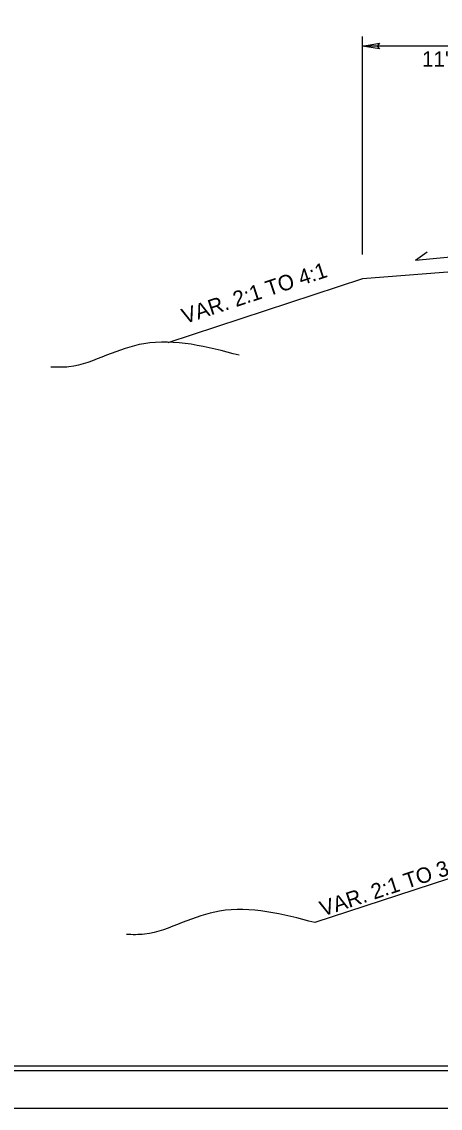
# Model space of a CAD drawing. Extents: x 2532463 to 2534146, y 189689 to 190784.
# Drawn here: x 2533037 to 2533260, y 189689 to 190267 of the extents above; entities that cross this region are included whole.
import ezdxf

# ---------------------------------------------------------------- set-up
doc = ezdxf.new("R2010")
doc.units = 0
for name, color, linetype in [('Old_Level_1', 7, 'Continuous'), ('Old_Level_10', 7, 'Continuous'), ('Old_Level_18', 7, 'Continuous'), ('Old_Level_2', 7, 'Continuous'), ('Old_Level_3', 7, 'Continuous'), ('Old_Level_42', 7, 'Continuous'), ('Old_Level_50', 7, 'Continuous'), ('Old_Level_51', 7, 'Continuous')]:
    doc.layers.add(name, color=color, linetype=linetype)

msp = doc.modelspace()

# ---------------------------------------------------------------- linework, layer by layer
at = {"layer": 'Old_Level_1'}
for p, q in [((2533296.94, 190136.17), (2533218.42, 190129.89)), ((2533218.42, 190129.89), (2533115.01, 190095.87)), ((2533296.48, 189821.84), (2533193.06, 189787.82))]:
    msp.add_line(p, q, dxfattribs=at)
at = {"layer": 'Old_Level_10'}
for points in [[(2533152.9, 190089.31), (2533102.29, 190095.45), (2533082.36, 190089.31), (2533062.42, 190083.18), (2533052.81, 190082.99)], [(2533193.06, 189787.82), (2533142.46, 189793.96), (2533122.52, 189787.82), (2533102.59, 189781.68), (2533092.97, 189781.5)]]:
    msp.add_spline(points, degree=3, dxfattribs=at)
at = {"layer": 'Old_Level_18'}
msp.add_lwpolyline([(2534129.31, 190761.68), (2532629.31, 190761.68), (2532629.31, 189711.68), (2534129.31, 189711.68)], close=True, dxfattribs=at)
at = {"layer": 'Old_Level_2'}
for p, q in [((2533218.42, 190142.94), (2533218.42, 190258.79)), ((2533329.41, 190253.64), (2533218.47, 190253.64)), ((2533246.54, 190139.83), (2533252.76, 190144.24)), ((2533246.54, 190139.83), (2533285.23, 190143.43))]:
    msp.add_line(p, q, dxfattribs=at)
at = {"layer": 'Old_Level_3'}
for p, q in [((2533218.47, 190253.64), (2533227.38, 190255.21)), ((2533227.38, 190252.07), (2533218.47, 190253.64)), ((2533227.38, 190255.21), (2533226.22, 190253.64)), ((2533226.22, 190253.64), (2533227.38, 190252.07))]:
    msp.add_line(p, q, dxfattribs=at)
at = {"layer": 'Old_Level_50'}
msp.add_lwpolyline([(2532475.81, 189709.18), (2534141.81, 189709.18), (2534141.81, 190764.18), (2532475.81, 190764.18)], close=True, dxfattribs=at)
at = {"layer": 'Old_Level_51'}
msp.add_lwpolyline([(2532462.81, 189689.18), (2534146.31, 189689.18), (2534146.31, 190784.18), (2532462.81, 190784.18)], close=True, dxfattribs=at)

# ---------------------------------------------------------------- texts
at = {"layer": 'Old_Level_2'}
msp.add_text("11'  W/GR", height=8.201, rotation=359.99988, dxfattribs=at).set_placement((2533250.04, 190242.63))
at = {"layer": 'Old_Level_42'}
for s, p in [('VAR. 2:1 TO 4:1', (2533123.98, 190105.9)), ('VAR. 2:1 TO 3:1', (2533197.34, 189791.03))]:
    msp.add_text(s, height=8.2009, rotation=18.25814, dxfattribs=at).set_placement(p)

doc.saveas('drawing.dxf')
